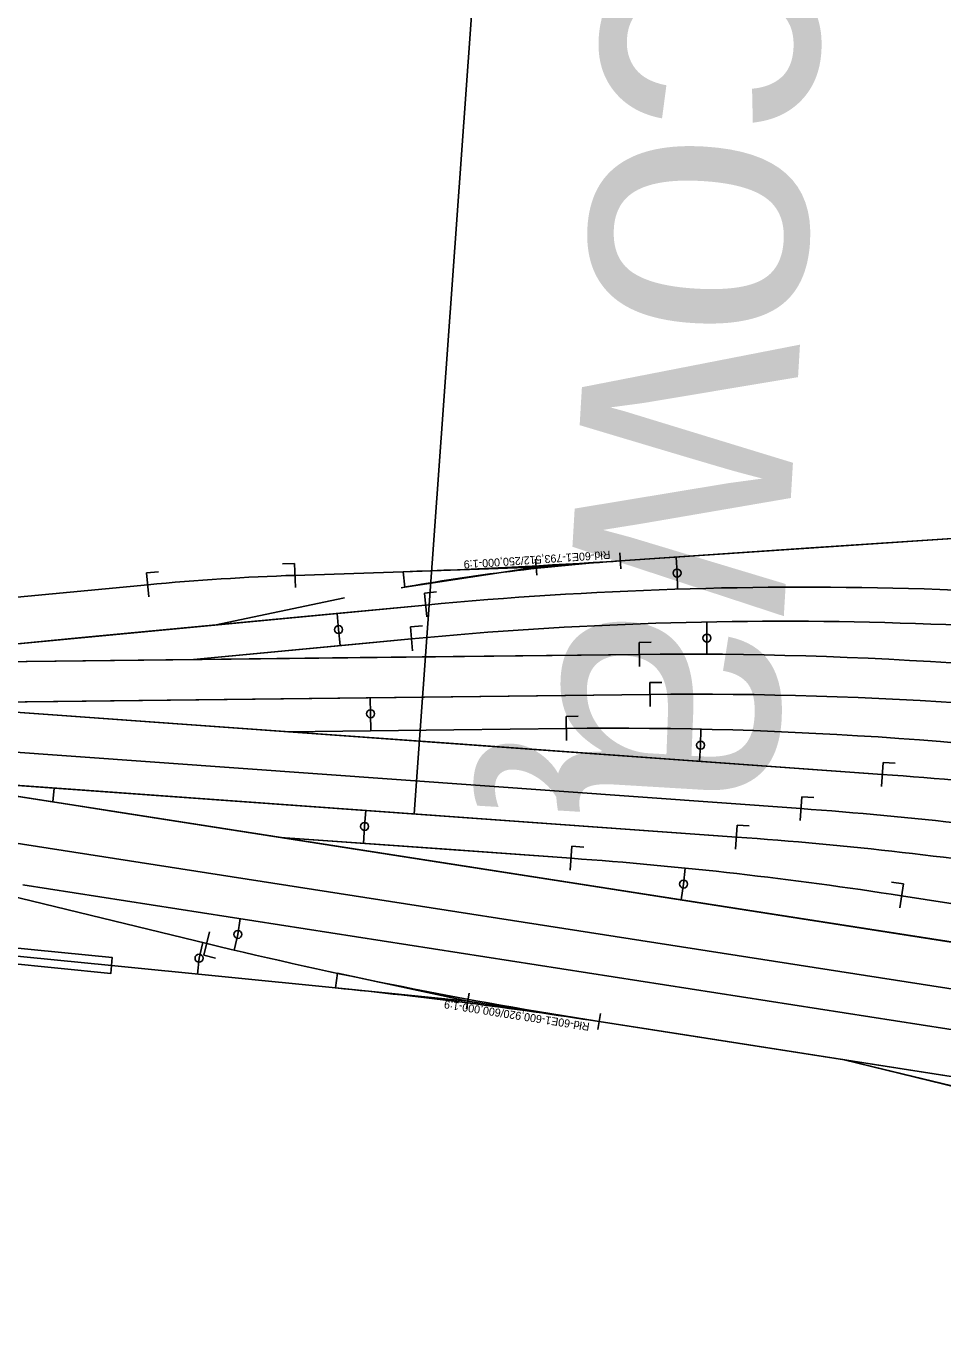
# Model space of a CAD drawing. Extents: x 6540402 to 6566579, y 5525343 to 5532423.
# Drawn here: x 6543781 to 6543895.5, y 5526482.9 to 5526647.2 of the extents above; entities that cross this region are included whole.
import ezdxf

# ---------------------------------------------------------------- set-up
doc = ezdxf.new("R2010")
doc.units = 0
for name, color, linetype in [('T_plan_koziol oporowy', 7, 'Continuous'), ('TOR_PS_OPIS_T-opisy dodatkowe', 7, 'Continuous'), ('TOR_PS_OPIS_T-symbole geometrii', 7, 'Continuous'), ('TOR_PS_OPIS_T-ukresy', 7, 'Continuous'), ('TOR_PS_T-rozjazdy projektowane', 7, 'Continuous'), ('TOR_PS_T-tory projektowane', 7, 'Continuous')]:
    doc.layers.add(name, color=color, linetype=linetype)

# ---------------------------------------------------------------- blocks, each defined once
blk = doc.blocks.new('koziol 15+5')
at = {"layer": 'T_plan_koziol oporowy'}
for p, q in [((15, 1), (14.3, 1)), ((15, 1), (15, -1)), ((20, 0), (20, 1)), ((0, 0), (15, 0)), ((15, -1), (14.3, -1))]:
    blk.add_line(p, q, dxfattribs=at)
blk.add_lwpolyline([(20, 1), (0, 1), (0, -1), (20, -1)], close=True, dxfattribs=at)

msp = doc.modelspace()

# ---------------------------------------------------------------- linework, layer by layer
at = {"layer": 'TOR_PS_OPIS_T-opisy dodatkowe'}
msp.add_line((6543882.78, 5527291.91), (6543829.47, 5526548.82), dxfattribs=at)
at = {"layer": 'TOR_PS_OPIS_T-symbole geometrii'}
for p, q in [((6543814.52, 5526580.13), (6543813.02, 5526580.08)), ((6543814.62, 5526577.13), (6543814.52, 5526580.13)), ((6543796.04, 5526578.95), (6543797.53, 5526579.09)), ((6543796.32, 5526575.96), (6543796.04, 5526578.95)), ((6543830.74, 5526576.42), (6543832.24, 5526576.56)), ((6543831.03, 5526573.43), (6543830.74, 5526576.42)), ((6543828.99, 5526572.2), (6543830.48, 5526572.34)), ((6543829.27, 5526569.21), (6543828.99, 5526572.2)), ((6543857.57, 5526570.26), (6543859.07, 5526570.28)), ((6543857.6, 5526567.26), (6543857.57, 5526570.26)), ((6543858.91, 5526565.24), (6543860.41, 5526565.26)), ((6543858.95, 5526562.24), (6543858.91, 5526565.24)), ((6543848.46, 5526561), (6543849.96, 5526561.02)), ((6543848.49, 5526558), (6543848.46, 5526561)), ((6543887.83, 5526552.27), (6543888.05, 5526555.27)), ((6543888.05, 5526555.27), (6543889.54, 5526555.16)), ((6543877.66, 5526547.99), (6543877.87, 5526550.98)), ((6543877.87, 5526550.98), (6543879.37, 5526550.88)), ((6543869.61, 5526544.44), (6543869.82, 5526547.43)), ((6543869.82, 5526547.43), (6543871.32, 5526547.33)), ((6543848.95, 5526541.79), (6543849.16, 5526544.79)), ((6543849.16, 5526544.79), (6543850.66, 5526544.68)), ((6543890.58, 5526540.08), (6543889.1, 5526540.31)), ((6543890.12, 5526537.11), (6543890.58, 5526540.08)), ((6543803.9, 5526534.09), (6543803.19, 5526531.18)), ((6543803.19, 5526531.18), (6543804.65, 5526530.82))]:
    msp.add_line(p, q, dxfattribs=at)
at = {"layer": 'TOR_PS_OPIS_T-ukresy'}
for p, q in [((6543862.3, 5526578.92), (6543862.17, 5526580.92)), ((6543862.3, 5526578.92), (6543862.36, 5526576.91)), ((6543820.02, 5526571.86), (6543819.83, 5526573.87)), ((6543866.03, 5526570.8), (6543866, 5526572.81)), ((6543820.02, 5526571.86), (6543820.21, 5526569.85)), ((6543866.03, 5526570.8), (6543866.02, 5526568.79)), ((6543824.01, 5526561.34), (6543823.98, 5526563.34)), ((6543824.01, 5526561.34), (6543824.03, 5526559.22)), ((6543865.24, 5526557.41), (6543865.28, 5526559.41)), ((6543865.24, 5526557.41), (6543865.09, 5526555.41)), ((6543823.27, 5526547.26), (6543823.42, 5526549.28)), ((6543823.27, 5526547.26), (6543823.12, 5526545.15)), ((6543863.11, 5526540.06), (6543863.31, 5526542.06)), ((6543863.11, 5526540.06), (6543862.8, 5526538.09)), ((6543807.43, 5526533.77), (6543807.74, 5526535.75)), ((6543807.43, 5526533.77), (6543806.97, 5526531.81)), ((6543802.58, 5526530.8), (6543803.05, 5526532.75)), ((6543802.58, 5526530.8), (6543802.38, 5526528.81))]:
    msp.add_line(p, q, dxfattribs=at)
for centre in [(6543862.3, 5526578.92), (6543820.02, 5526571.86), (6543866.03, 5526570.8), (6543824.01, 5526561.34), (6543865.24, 5526557.41), (6543823.27, 5526547.26), (6543863.11, 5526540.06), (6543807.43, 5526533.77), (6543802.58, 5526530.8)]:
    msp.add_circle(centre, 0.5, dxfattribs=at)
msp.add_arc((6543591.15, 5527080.65), 500, 261.1322, 261.1322, dxfattribs=at)
at = {"layer": 'TOR_PS_T-rozjazdy projektowane'}
for p, q in [((6543855.26, 5526579.45), (6543855.13, 5526581.44)), ((6543844.77, 5526578.66), (6543844.63, 5526580.66)), ((6543836.31, 5526526.43), (6543836, 5526524.46)), ((6543852.73, 5526523.87), (6543852.42, 5526521.89))]:
    msp.add_line(p, q, dxfattribs=at)
for points in [[(6543855.19, 5526580.45), (6543844.7, 5526579.66), (6543828.28, 5526577.16), (6543828.1, 5526579.08), (6543844.7, 5526579.66)], [(6543743.2, 5526556.75), (6543763.75, 5526553.54), (6543784.3, 5526550.33), (6543784.49, 5526552.05), (6543763.75, 5526553.54)], [(6543819.9, 5526528.91), (6543836.15, 5526525.44), (6543852.57, 5526522.88), (6543836.15, 5526525.44), (6543819.62, 5526527.09)]]:
    msp.add_lwpolyline(points, close=True, dxfattribs=at)
at = {"layer": 'TOR_PS_T-tory projektowane'}
for p, q in [((6543923.59, 5526585.06), (6543855.19, 5526580.45)), ((6543923.59, 5526585.06), (6543879.03, 5526582.06)), ((6543906.1, 5526583.88), (6543879.03, 5526582.06)), ((6543879.03, 5526582.06), (6543855.19, 5526580.45)), ((6543828.09, 5526579.08), (6543814.57, 5526578.63)), ((6543796.18, 5526577.45), (6543778.99, 5526575.82)), ((6544194.47, 5526486.34), (6543624.83, 5526575.21)), ((6543830.89, 5526574.92), (6543753.32, 5526567.56)), ((6543830.89, 5526574.92), (6543774.02, 5526569.53)), ((6543830.89, 5526574.92), (6543787.96, 5526570.85)), ((6543820.77, 5526575.81), (6543804.5, 5526572.42)), ((6543830.89, 5526574.92), (6543821.04, 5526573.99)), ((6544194.47, 5526486.34), (6543634.71, 5526573.67)), ((6543821.04, 5526573.99), (6543787.96, 5526570.85)), ((6543887.94, 5526553.77), (6543655.26, 5526570.47)), ((6543787.96, 5526570.85), (6543774.02, 5526569.53)), ((6543829.13, 5526570.7), (6543801.91, 5526568.12)), ((6543822.61, 5526570.08), (6543801.91, 5526568.12)), ((6543829.13, 5526570.7), (6543822.61, 5526570.08)), ((6544105.35, 5526494.37), (6543634.03, 5526567.91)), ((6543887.94, 5526553.77), (6543676, 5526568.98)), ((6543887.94, 5526553.77), (6543682.98, 5526568.48)), ((6543857.59, 5526568.76), (6543703.73, 5526566.99)), ((6543857.59, 5526568.76), (6543724.52, 5526567.23)), ((6543857.59, 5526568.76), (6543732.52, 5526567.32)), ((6543857.59, 5526568.76), (6543774.11, 5526567.8)), ((6543781.11, 5526567.88), (6543774.11, 5526567.8)), ((6543857.59, 5526568.76), (6543781.11, 5526567.88)), ((6543822.71, 5526568.36), (6543781.11, 5526567.88)), ((6543857.59, 5526568.76), (6543822.71, 5526568.36)), ((6544194.47, 5526486.34), (6543675.81, 5526567.26)), ((6543887.94, 5526553.77), (6543724.47, 5526565.5)), ((6544194.47, 5526486.34), (6543694.2, 5526564.39)), ((6543887.94, 5526553.77), (6543743.42, 5526564.14)), ((6543784.91, 5526561.16), (6543743.42, 5526564.14)), ((6543858.93, 5526563.74), (6543764.17, 5526562.65)), ((6543784.96, 5526562.89), (6543764.17, 5526562.65)), ((6543858.93, 5526563.74), (6543784.96, 5526562.89)), ((6543877.77, 5526549.49), (6543714.75, 5526561.19)), ((6543877.77, 5526549.49), (6543735.49, 5526559.7)), ((6543887.94, 5526553.77), (6543784.91, 5526561.16)), ((6543792.89, 5526560.59), (6543784.91, 5526561.16)), ((6543887.94, 5526553.77), (6543792.89, 5526560.59)), ((6543834.38, 5526557.61), (6543792.89, 5526560.59)), ((6544194.47, 5526486.34), (6543735.29, 5526557.98)), ((6543834.43, 5526559.34), (6543813.63, 5526559.1)), ((6543848.47, 5526559.5), (6543834.43, 5526559.34)), ((6544194.47, 5526486.34), (6543743.2, 5526556.75)), ((6543784.3, 5526550.33), (6543743.2, 5526556.75)), ((6543887.94, 5526553.77), (6543834.38, 5526557.61)), ((6543869.72, 5526545.94), (6543763.75, 5526553.54)), ((6543784.49, 5526552.05), (6543763.75, 5526553.54)), ((6543869.72, 5526545.94), (6543784.49, 5526552.05)), ((6544194.47, 5526486.34), (6543784.3, 5526550.33)), ((6543792.2, 5526549.1), (6543784.3, 5526550.33)), ((6544194.47, 5526486.34), (6543792.2, 5526549.1)), ((6543833.3, 5526542.69), (6543792.2, 5526549.1)), ((6543849.06, 5526543.29), (6543812.75, 5526545.89)), ((6543833.49, 5526544.41), (6543812.75, 5526545.89)), ((6543760.02, 5526543.19), (6543803.54, 5526532.63)), ((6543849.06, 5526543.29), (6543833.49, 5526544.41)), ((6544194.47, 5526486.34), (6543833.3, 5526542.69)), ((6544062.61, 5526495.98), (6543780.57, 5526539.98)), ((6543780.23, 5526538.29), (6543803.54, 5526532.63)), ((6544197.83, 5526490.62), (6543890.35, 5526538.6)), ((6543819.62, 5526527.09), (6543791.65, 5526529.88)), ((6543852.56, 5526522.88), (6544108.92, 5526482.89)), ((6543852.56, 5526522.88), (6543862.46, 5526521.34)), ((6543862.46, 5526521.34), (6544108.92, 5526482.89)), ((6543862.46, 5526521.34), (6543903.56, 5526514.93)), ((6543986.26, 5526493.09), (6543883.01, 5526518.13)), ((6543903.22, 5526513.23), (6543883.01, 5526518.13))]:
    msp.add_line(p, q, dxfattribs=at)
for centre, radius, start, end in [((6543872.03, 5526331.01), 250, 93.8626, 100.1868), ((6543801.74, 5527372.16), 793.51, 271.90314, 273.86265), ((6543824.53, 5526278.8), 300, 91.9031, 95.4232), ((6543878.14, 5526077.16), 500, 81.1323, 95.4232), ((6543875.44, 5526082.9), 490, 81.1323, 95.4232), ((6543863.34, 5526068.79), 500, 81.1323, 90.6595), ((6543864.68, 5526063.78), 500, 81.1323, 90.6595), ((6543854.23, 5526059.54), 500, 81.1323, 90.6595), ((6543852.15, 5526055.05), 500, 81.1323, 85.8959), ((6543841.98, 5526050.77), 500, 81.1323, 85.8959), ((6543833.93, 5526047.22), 500, 81.1323, 85.8959), ((6543813.27, 5526044.57), 500, 81.1323, 85.8959), ((6543945.2, 5527116.62), 600.92, 256.36541, 261.13225), ((6543760.09, 5525930.05), 600, 81.13225, 84.30548)]:
    msp.add_arc(centre, radius, start, end, dxfattribs=at)

# ---------------------------------------------------------------- block references
at = {"layer": 'T_plan_koziol oporowy', "rotation": 174.30548204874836}
msp.add_blockref('koziol 15+5', (6543791.65, 5526529.88), dxfattribs=at)

# ---------------------------------------------------------------- texts
at = {"layer": 'TOR_PS_OPIS_T-opisy dodatkowe'}
msp.add_text('Wiadukt kolejowy nad ul. Dworcową', height=35, rotation=266.5957, dxfattribs=at).set_placement((6543891.6, 5527294.51))
at = {"layer": 'TOR_PS_T-rozjazdy projektowane'}
for s, rotation, p in [('Rłd-60E1-793,512/250,000-1:9', 183.8626, (6543853.94, 5526581.71)), ('Rłd-60E1-600,920/600,000-1:9', 171.1225, (6543851.43, 5526522.71))]:
    msp.add_text(s, height=1, rotation=rotation, dxfattribs=at).set_placement(p)

doc.saveas('drawing.dxf')
